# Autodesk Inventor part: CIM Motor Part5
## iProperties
Created: 2010-01
Part Number: CIM Motor Part5
Document SubType Name: Modeling
Designer: cmcfadden
Density: 1 g/cm^3
Author: cmcfadden
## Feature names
1. Extrusion1
2. Extrusion2
3. Extrusion3
4. Chamfer1
